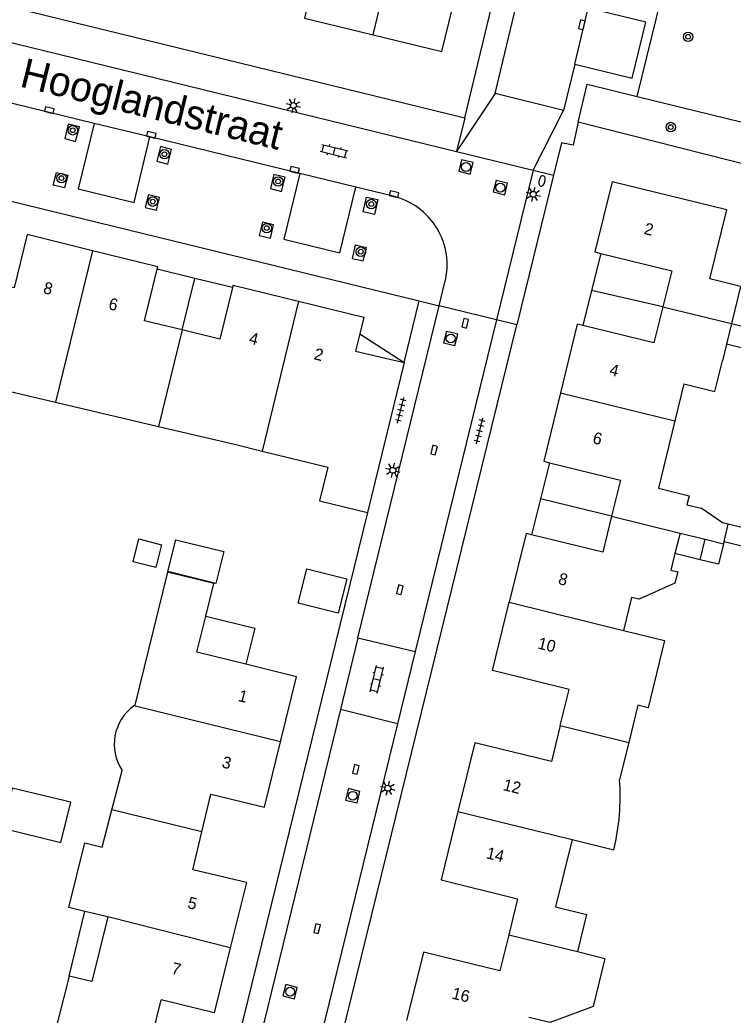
# Model space of a CAD drawing. Extents: x 128000 to 131008, y 398996 to 402500.
# Drawn here: x 128527.8 to 128588.3, y 399472.9 to 399557.4 of the extents above; entities that cross this region are included whole.
import ezdxf

# ---------------------------------------------------------------- set-up
doc = ezdxf.new("R2010")
doc.units = 0
for name, color, linetype in [('gg-afsc-erfafscheiding', 7, 'Continuous'), ('gg-anno-huisnummerreeks BGT', 7, 'Continuous'), ('gg-anno-openbare ruimte label', 7, 'Continuous'), ('gg-bbg-gedigitaliseerde bebouwing', 7, 'Continuous'), ('gg-bbg-gedigitaliseerde bijgebouw', 7, 'Continuous'), ('gg-bbg-hoofdgebouw', 7, 'Continuous'), ('gg-bbg-luifel en loopbrug', 7, 'Continuous'), ('gg-bbg-tussenscheiding', 7, 'Continuous'), ('gg-knt-verharding', 7, 'Continuous'), ('gg-knt-verharding nz', 7, 'Continuous'), ('gt-grn-groengrens', 7, 'Continuous'), ('gt-grn-weggrens', 7, 'Continuous'), ('gt-symb-boom', 7, 'Continuous'), ('gt-symb-brandkraan', 7, 'Continuous'), ('gt-symb-klinker verharding', 7, 'Continuous'), ('gt-symb-kolk', 7, 'Continuous'), ('gt-symb-lichtmast', 7, 'Continuous'), ('gt-symb-rioolschacht', 7, 'Continuous'), ('gt-symb-tegel verharding', 7, 'Continuous')]:
    doc.layers.add(name, color=color, linetype=linetype)

# ---------------------------------------------------------------- blocks, each defined once
blk = doc.blocks.new('gt0-BOOM')
at = {"layer": 'gt-symb-boom'}
for radius in [0.4, 0.2]:
    blk.add_circle((0, 0), radius, dxfattribs=at)
blk = doc.blocks.new('gt0-RS')
at = {"layer": 'gt-symb-rioolschacht'}
blk.add_lwpolyline([(-0.5, -0.5), (0.5, -0.5), (0.5, 0.5), (-0.5, 0.5)], close=True, dxfattribs=at)
blk.add_circle((0, 0), 0.375, dxfattribs=at)
blk = doc.blocks.new('gt0-KOLK')
at = {"layer": 'gt-symb-kolk'}
blk.add_lwpolyline([(0, 0), (0.375, 0), (0.375, 0.4), (-0.375, 0.4), (-0.375, 0), (0, 0)], dxfattribs=at)
blk = doc.blocks.new('gt0-LMAST')
at = {"layer": 'gt-symb-lichtmast'}
for p, q in [((-0.182, 0.173), (-0.447, 0.438)), ((-0.005, 0.246), (-0.005, 0.621)), ((0.172, 0.173), (0.437, 0.438)), ((-0.255, -0.004), (-0.63, -0.004)), ((-0.182, -0.181), (-0.447, -0.446)), ((-0.005, -0.254), (-0.005, -0.629)), ((0.437, -0.446), (0.172, -0.181)), ((0.245, -0.004), (0.62, -0.004))]:
    blk.add_line(p, q, dxfattribs=at)
blk.add_circle((-0.005, -0.004), 0.25, dxfattribs=at)
blk = doc.blocks.new('gt0-BR')
at = {"layer": 'gt-symb-brandkraan'}
for centre, radius, start, end in [((-0.244, 0), 0.206, 107.56694, 252.43307), ((0.599, -2.664), 3, 106.89205, 107.56694), ((0, -0.691), 0.938, 73.10799, 106.89205), ((-0.599, -2.664), 3, 72.43309, 73.10799), ((0.244, 0), 0.206, 287.56695, 72.43309), ((0.599, 2.664), 3, 252.43307, 253.10797), ((0, 0.691), 0.938, 253.10797, 286.89206), ((-0.599, 2.664), 3, 286.89206, 287.56695)]:
    blk.add_arc(centre, radius, start, end, dxfattribs=at)
blk = doc.blocks.new('gt0-KL1')
at = {"layer": 'gt-symb-klinker verharding'}
for p, q in [((-1.15, 0.3), (1.15, 0.3)), ((-1, -0.3), (-1, 0.3)), ((-0.5, 0.3), (-0.5, 0.45)), ((0, -0.3), (0, 0.3)), ((0.5, 0.3), (0.5, 0.45)), ((1, -0.3), (1, 0.3)), ((-1.15, -0.3), (1.15, -0.3)), ((-0.5, -0.45), (-0.5, -0.3)), ((0.5, -0.45), (0.5, -0.3))]:
    blk.add_line(p, q, dxfattribs=at)
blk = doc.blocks.new('gt0-TEG1')
at = {"layer": 'gt-symb-tegel verharding'}
for p, q in [((-1.125, 0), (1.125, 0)), ((-0.9, -0.25), (-0.9, 0.25)), ((-0.45, -0.25), (-0.45, 0.25)), ((0, -0.25), (0, 0.25)), ((0.45, -0.25), (0.45, 0.25)), ((0.9, -0.25), (0.9, 0.25))]:
    blk.add_line(p, q, dxfattribs=at)

msp = doc.modelspace()

# ---------------------------------------------------------------- linework, layer by layer
at = {"layer": 'gg-afsc-erfafscheiding'}
msp.add_line((128602.685, 399541.745), (128575.165, 399548.745), dxfattribs=at)
at = {"layer": 'gg-bbg-gedigitaliseerde bebouwing'}
for p, q in [((128588.94, 399534.81), (128588.165, 399531.649)), ((128587.736, 399529.901), (128587.391, 399528.493)), ((128522.034, 399527.045), (128530.82, 399524.977)), ((128584.13, 399526.528), (128583.363, 399523.398)), ((128530.82, 399524.977), (128539.556, 399522.921)), ((128584.385, 399516.271), (128585.599, 399515.973)), ((128583.797, 399513.872), (128583.369, 399512.124)), ((128583.797, 399513.872), (128585.934, 399513.348)), ((128583.369, 399512.124), (128583.024, 399510.716)), ((128579.679, 399508.406), (128578.992, 399505.602)), ((128537.541, 399499.263), (128537.441, 399499.192)), ((128580.224, 399499.246), (128579.45, 399496.09)), ((128579.45, 399496.09), (128578.677, 399492.934)), ((128535.595, 399490.382), (128536.458, 399493.72)), ((128534.777, 399487.217), (128535.595, 399490.382)), ((128574.643, 399487.852), (128578.183, 399486.982)), ((128535.234, 399481.281), (128533.3, 399481.754))]:
    msp.add_line(p, q, dxfattribs=at)
for points in [[(128584.13, 399526.528), (128586.749, 399525.885), (128587.391, 399528.493)], [(128583.363, 399523.398), (128581.959, 399517.668), (128584.571, 399517.028), (128584.385, 399516.271)], [(128539.556, 399522.921), (128545.986, 399521.408), (128548.337, 399520.831)], [(128548.337, 399520.831), (128553.907, 399519.466), (128553.204, 399516.601), (128557.27, 399515.604)], [(128587.893, 399514.618), (128587.399, 399514.739), (128585.599, 399515.973)], [(128583.024, 399510.716), (128583.607, 399510.573), (128583.368, 399509.602), (128580.344, 399508.243), (128579.679, 399508.406)], [(128578.992, 399505.602), (128582.49, 399504.749), (128581.096, 399499.033), (128580.224, 399499.246)], [(128574.643, 399487.852), (128573.243, 399482.141), (128575.865, 399481.498), (128575.089, 399478.333)], [(128533.3, 399481.754), (128531.945, 399482.085), (128533.289, 399487.581), (128534.777, 399487.217)], [(128575.089, 399478.333), (128577.42, 399477.761), (128576.419, 399473.682), (128572.787, 399472.308), (128570.963, 399472.755)]]:
    msp.add_lwpolyline(points, dxfattribs=at)
for centre, radius, start, end in [((128539.815, 399495.941), 4.025, 126.13714, 213.49467), ((128559.122, 399491.56), 19.603, 346.49316, 4.0178)]:
    msp.add_arc(centre, radius, start, end, dxfattribs=at)
at = {"layer": 'gg-bbg-gedigitaliseerde bijgebouw'}
for p, q in [((128588.165, 399531.649), (128592.05, 399530.696)), ((128591.621, 399528.948), (128587.736, 399529.901)), ((128585.505, 399511.6), (128585.934, 399513.348)), ((128587.488, 399512.967), (128587.535, 399513.161))]:
    msp.add_line(p, q, dxfattribs=at)
for points in [[(128587.535, 399513.161), (128589.381, 399512.709), (128589.738, 399514.165), (128587.893, 399514.618)], [(128537.87, 399513.365), (128539.81, 399512.881), (128539.326, 399510.94), (128537.386, 399511.424), (128537.87, 399513.365)], [(128587.488, 399512.967), (128587.059, 399511.219), (128585.505, 399511.6)], [(128552.132, 399510.831), (128555.528, 399509.984), (128554.802, 399507.073), (128551.406, 399507.921), (128552.132, 399510.831)]]:
    msp.add_lwpolyline(points, dxfattribs=at)
at = {"layer": 'gg-bbg-hoofdgebouw'}
for p, q in [((128533.945, 399537.84), (128528.41, 399539.2)), ((128539.48, 399536.48), (128533.945, 399537.84)), ((128539.431, 399536.279), (128539.48, 399536.48)), ((128545.89, 399534.92), (128545.838, 399534.706)), ((128545.89, 399534.92), (128551.431, 399533.566)), ((128551.431, 399533.566), (128556.98, 399532.21)), ((128556.98, 399532.21), (128556.626, 399530.768)), ((128556.626, 399530.768), (128556.269, 399529.311)), ((128556.269, 399529.311), (128560.383, 399528.334)), ((128560.383, 399528.334), (128557.27, 399515.604)), ((128551.27, 399501.67), (128546.958, 399502.728)), ((128549.91, 399496.135), (128551.27, 399501.67)), ((128548.55, 399490.6), (128549.91, 399496.135)), ((128547, 399484.2), (128545.638, 399478.661)), ((128531.955, 399476.264), (128530.462, 399470.328)), ((128538.339, 399468.41), (128539.762, 399474.242))]:
    msp.add_line(p, q, dxfattribs=at)
for points in [[(128550.44, 399564.846), (128553.51, 399564.1), (128551.93, 399557.59), (128557.768, 399556.164)], [(128557.768, 399556.164), (128563.6, 399554.74), (128565.18, 399561.26), (128568.29, 399560.5)], [(128588.94, 399534.81), (128586.33, 399535.45), (128587.76, 399541.3), (128578.04, 399543.68), (128576.58, 399537.73), (128577.066, 399537.611)], [(128528.41, 399539.2), (128527.3, 399534.684), (128524.047, 399535.484)], [(128577.066, 399537.611), (128583.09, 399536.13), (128582.34, 399533.075)], [(128541.563, 399531.115), (128538.355, 399531.896), (128539.431, 399536.279)], [(128545.838, 399534.706), (128544.765, 399530.336), (128541.563, 399531.115)], [(128582.34, 399533.075), (128581.59, 399530.02), (128575.562, 399531.492)], [(128575.562, 399531.492), (128575.08, 399531.61), (128573.655, 399525.784)], [(128573.655, 399525.784), (128572.23, 399519.96), (128572.716, 399519.841)], [(128572.716, 399519.841), (128578.74, 399518.36), (128577.991, 399515.304)], [(128577.991, 399515.304), (128577.24, 399512.24), (128571.209, 399513.713)], [(128571.209, 399513.713), (128570.73, 399513.83), (128569.305, 399508.012)], [(128543.565, 399506.819), (128544.246, 399509.592), (128540.312, 399510.557), (128537.541, 399499.263)], [(128573.637, 399497.525), (128574.39, 399500.6), (128567.88, 399502.19), (128569.305, 399508.012)], [(128546.958, 399502.728), (128542.811, 399503.746), (128543.565, 399506.819)], [(128573.637, 399497.525), (128572.89, 399494.47), (128566.38, 399496.06), (128564.951, 399490.243)], [(128543.235, 399488.513), (128544, 399491.695), (128548.55, 399490.6)], [(128564.951, 399490.243), (128563.52, 399484.42), (128570.02, 399482.83), (128569.269, 399479.766)], [(128547, 399484.2), (128542.46, 399485.292), (128543.235, 399488.513)], [(128535.234, 399481.281), (128533.898, 399475.791), (128531.955, 399476.264)], [(128569.269, 399479.766), (128568.52, 399476.71), (128562.02, 399478.3), (128560.59, 399472.476)], [(128545.638, 399478.661), (128544.28, 399473.14), (128539.762, 399474.242)]]:
    msp.add_lwpolyline(points, dxfattribs=at)
at = {"layer": 'gg-bbg-luifel en loopbrug'}
for p, q in [((128577.066, 399537.611), (128576.291, 399534.459)), ((128542.637, 399535.492), (128539.431, 399536.279)), ((128541.563, 399531.115), (128542.637, 399535.492)), ((128545.838, 399534.706), (128542.637, 399535.492)), ((128576.291, 399534.459), (128575.562, 399531.492)), ((128582.34, 399533.075), (128576.291, 399534.459)), ((128556.626, 399530.768), (128560.383, 399528.334)), ((128572.716, 399519.841), (128571.965, 399516.785)), ((128571.965, 399516.785), (128571.209, 399513.713)), ((128577.991, 399515.304), (128571.965, 399516.785)), ((128585.505, 399511.6), (128583.369, 399512.124)), ((128531.955, 399476.264), (128533.3, 399481.754))]:
    msp.add_line(p, q, dxfattribs=at)
for points in [[(128541.016, 399513.307), (128545.091, 399512.291), (128544.414, 399509.574), (128540.339, 399510.591), (128541.016, 399513.307)], [(128543.565, 399506.819), (128547.713, 399505.801), (128546.958, 399502.728)], [(128526.309, 399488.826), (128531.27, 399487.61), (128532.103, 399491.01), (128527.142, 399492.225), (128526.309, 399488.826)]]:
    msp.add_lwpolyline(points, dxfattribs=at)
at = {"layer": 'gg-bbg-tussenscheiding'}
for p, q in [((128557.768, 399556.164), (128560.782, 399568.731)), ((128533.945, 399537.84), (128530.82, 399524.977)), ((128551.431, 399533.566), (128548.337, 399520.831)), ((128582.34, 399533.075), (128588.165, 399531.649)), ((128541.563, 399531.115), (128539.556, 399522.921)), ((128588.165, 399531.649), (128587.736, 399529.901)), ((128573.655, 399525.784), (128583.363, 399523.398)), ((128577.991, 399515.304), (128583.797, 399513.872)), ((128587.535, 399513.161), (128587.893, 399514.618)), ((128585.934, 399513.348), (128587.488, 399512.967)), ((128569.305, 399508.012), (128578.992, 399505.602)), ((128549.91, 399496.135), (128537.441, 399499.192)), ((128573.637, 399497.525), (128579.45, 399496.09)), ((128543.235, 399488.513), (128535.595, 399490.382)), ((128564.951, 399490.243), (128574.643, 399487.852)), ((128545.638, 399478.661), (128535.234, 399481.281)), ((128569.269, 399479.766), (128575.089, 399478.333))]:
    msp.add_line(p, q, dxfattribs=at)
at = {"layer": 'gg-knt-verharding'}
for p, q in [((128568.1, 399551.17), (128573.38, 399573.081)), ((128565.53, 399549.13), (128568.29, 399560.5)), ((128515.154, 399558.42), (128564.831, 399546.272)), ((128574.86, 399553.679), (128573.91, 399549.75)), ((128534.082, 399548.646), (128521.301, 399551.763)), ((128573.91, 399549.75), (128568.1, 399551.17)), ((128551.529, 399544.39), (128538.814, 399547.492)), ((128564.831, 399546.272), (128571.34, 399544.68)), ((128571.34, 399544.68), (128568.225, 399531.97)), ((128573.069, 399544.256), (128569.948, 399531.547)), ((128559.45, 399542.46), (128556.284, 399543.23)), ((128563.363, 399533.164), (128563.85, 399535.154)), ((128556.465, 399504.962), (128563.363, 399533.164)), ((128568.225, 399531.97), (128561.325, 399503.817)), ((128553.44, 399464.32), (128569.948, 399531.547)), ((128557.27, 399515.604), (128545.27, 399466.69)), ((128556.465, 399504.962), (128554.983, 399498.903)), ((128556.465, 399504.962), (128561.325, 399503.817)), ((128561.325, 399503.817), (128559.819, 399497.669)), ((128554.983, 399498.903), (128546.284, 399463.342)), ((128559.819, 399497.669), (128554.983, 399498.903)), ((128559.819, 399497.669), (128551.744, 399464.72))]:
    msp.add_line(p, q, dxfattribs=at)
for points in [[(128580.17, 399550.92), (128585.11, 399571.1), (128584.13, 399571.32)], [(128512.692, 399564.8), (128512.06, 399562.22), (128565.53, 399549.13)], [(128574.86, 399553.679), (128579.725, 399552.487), (128580.89, 399557.235), (128576.009, 399558.428)], [(128575.165, 399548.745), (128575.91, 399551.98), (128580.17, 399550.92)], [(128575.165, 399548.745), (128574.72, 399546.811), (128573.74, 399546.99), (128573.069, 399544.256)], [(128532.847, 399548.352), (128531.886, 399548.591), (128531.586, 399547.374), (128532.51, 399547.116), (128532.847, 399548.352)], [(128534.082, 399548.646), (128532.721, 399543.082), (128537.471, 399541.932), (128538.814, 399547.492)], [(128539.396, 399545.426), (128540.335, 399545.193), (128540.636, 399546.435), (128539.715, 399546.676), (128539.396, 399545.426)], [(128531.852, 399544.249), (128531.582, 399543.184), (128530.619, 399543.41), (128530.902, 399544.49), (128531.852, 399544.249)], [(128550.298, 399544.09), (128549.337, 399544.315), (128549.045, 399543.131), (128549.982, 399542.872), (128550.298, 399544.09)], [(128551.529, 399544.39), (128550.183, 399538.826), (128554.927, 399537.667), (128556.284, 399543.23)], [(128539.641, 399542.361), (128538.7, 399542.588), (128538.416, 399541.514), (128539.38, 399541.269), (128539.641, 399542.361)], [(128557.862, 399540.899), (128556.916, 399541.136), (128557.207, 399542.396), (128558.158, 399542.18), (128557.862, 399540.899)], [(128549.318, 399540.04), (128548.369, 399540.272), (128548.083, 399539.131), (128549.038, 399538.9), (128549.318, 399540.04)], [(128556.247, 399538.302), (128555.979, 399537.179), (128556.922, 399536.965), (128557.189, 399538.076), (128556.247, 399538.302)]]:
    msp.add_lwpolyline(points, dxfattribs=at)
msp.add_arc((128558.045, 399536.636), 5.992, 345.68275, 76.43371, dxfattribs=at)
at = {"layer": 'gg-knt-verharding nz'}
for p, q in [((128574.86, 399553.679), (128576.009, 399558.428)), ((128538.814, 399547.492), (128534.082, 399548.646)), ((128556.284, 399543.23), (128551.529, 399544.39))]:
    msp.add_line(p, q, dxfattribs=at)
at = {"layer": 'gt-grn-groengrens'}
msp.add_line((128580.17, 399550.92), (128603.493, 399545.21), dxfattribs=at)
at = {"layer": 'gt-grn-weggrens'}
for p, q in [((128568.1, 399551.17), (128564.831, 399546.272)), ((128571.34, 399544.68), (128573.91, 399549.75)), ((128565.53, 399549.13), (128564.831, 399546.272)), ((128508.26, 399546.64), (128561.67, 399533.58)), ((128571.34, 399544.68), (128573.069, 399544.256)), ((128560.383, 399528.334), (128561.67, 399533.58)), ((128561.67, 399533.58), (128563.363, 399533.164)), ((128568.225, 399531.97), (128563.363, 399533.164)), ((128569.948, 399531.547), (128568.225, 399531.97))]:
    msp.add_line(p, q, dxfattribs=at)

# ---------------------------------------------------------------- block references
at = {"layer": 'gt-symb-boom'}
for p in [(128584.486, 399555.999), (128583.015, 399548.336), (128532.274, 399548.06), (128540.055, 399546.028), (128531.311, 399544), (128549.698, 399543.714), (128539.065, 399542.002), (128557.606, 399541.801), (128548.728, 399539.756), (128556.711, 399537.755)]:
    msp.add_blockref('gt0-BOOM', p, dxfattribs=at)
at = {"layer": 'gt-symb-brandkraan', "rotation": -103.59156043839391}
msp.add_blockref('gt0-BR', (128572.089, 399543.765), dxfattribs=at)
at = {"layer": 'gt-symb-klinker verharding'}
for p, rotation in [((128554.465, 399546.293), -13.772145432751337), ((128558.077, 399501.43), 76.28353067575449)]:
    msp.add_blockref('gt0-KL1', p, dxfattribs=dict(at, rotation=rotation))
at = {"layer": 'gt-symb-kolk'}
for p, rotation in [((128575.269, 399557.059), -103.59156043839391), ((128530.239, 399549.583), -13.702889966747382), ((128538.883, 399547.475), -13.702889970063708), ((128551.044, 399544.508), -13.702889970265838), ((128559.489, 399542.448), -13.702889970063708), ((128565.368, 399531.729), -103.59156043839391), ((128562.735, 399520.955), -103.59156043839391), ((128559.84, 399509.1), -103.59156043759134), ((128556.489, 399493.756), 76.17220496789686), ((128553.194, 399480.234), 76.17220496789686)]:
    msp.add_blockref('gt0-KOLK', p, dxfattribs=dict(at, rotation=rotation))
at = {"layer": 'gt-symb-lichtmast'}
for p, rotation in [((128551.002, 399550.165), -13.702889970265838), ((128571.35, 399542.619), -103.59156043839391), ((128559.43, 399519.192), -103.59156044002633), ((128558.995, 399492.209), 76.17220496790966)]:
    msp.add_blockref('gt0-LMAST', p, dxfattribs=dict(at, rotation=rotation))
at = {"layer": 'gt-symb-rioolschacht'}
for p, rotation in [((128565.636, 399544.946), 76.22785456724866), ((128568.553, 399543.191), 76.22785456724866), ((128564.337, 399530.386), 76.22785456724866), ((128556.031, 399491.565), 76.22785456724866), ((128550.715, 399474.937), -103.77214543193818)]:
    msp.add_blockref('gt0-RS', p, dxfattribs=dict(at, rotation=rotation))
at = {"layer": 'gt-symb-tegel verharding', "rotation": 76.22785456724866}
for p in [(128560.107, 399524.288), (128566.795, 399522.534)]:
    msp.add_blockref('gt0-TEG1', p, dxfattribs=at)

# ---------------------------------------------------------------- texts
at = {"layer": 'gg-anno-huisnummerreeks BGT'}
for s, rotation, p in [('2', 346.2, (128580.677, 399539.27)), ('8', 346.2, (128529.704, 399534.248)), ('6', 346.2, (128535.239, 399532.888)), ('4', 346.3, (128547.158, 399529.977)), ('2', 346.3, (128552.671, 399528.63)), ('4', 346.2, (128577.743, 399527.297)), ('6', 346.2, (128576.327, 399521.507)), ('8', 346.2, (128573.401, 399509.555)), ('10', 346.2, (128571.66, 399504.078)), ('1', 346.2, (128546.248, 399499.624)), ('3', 346.2, (128544.863, 399493.986)), ('12', 346.2, (128568.715, 399492.059)), ('14', 346.2, (128567.293, 399486.27)), ('5', 346.2, (128541.952, 399482.05)), ('7', 346.2, (128540.582, 399476.481)), ('16', 346.2, (128564.372, 399474.363))]:
    msp.add_text(s, height=1, rotation=rotation, dxfattribs=at).set_placement(p)
at = {"layer": 'gg-anno-openbare ruimte label'}
msp.add_text('Hooglandstraat', height=2.5, rotation=346.2, dxfattribs=at).set_placement((128527.681, 399551.797))

doc.saveas('drawing.dxf')
